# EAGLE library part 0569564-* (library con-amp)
MODULAR JACK 8 POS., RIGHT ANGLE, LOW PROFILE WITH LEDS Source: http://ecommas.tycoelectronics.com/.. 569564_K.pdf
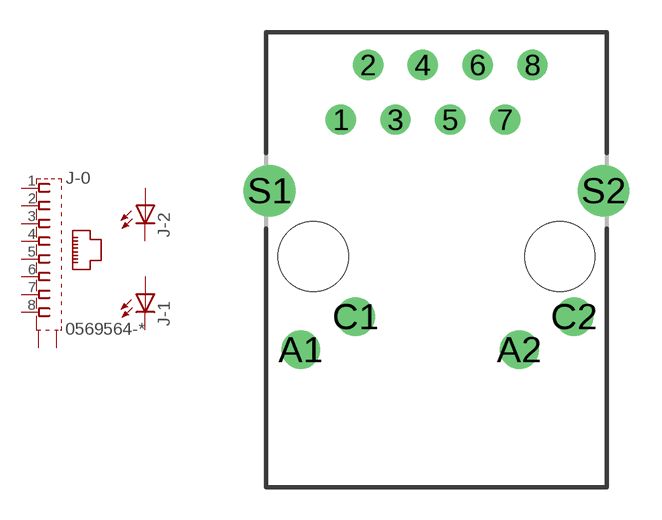
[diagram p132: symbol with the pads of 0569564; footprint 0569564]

Designator prefix J; gates -0=JACK8SH -1=LED -2=LED

## 0569564-1 (MF: TYCO ELECTRONICS; MPN: 569564-1; OC_FARNELL: 1375079; OC_NEWARK: 34B457), 0569564-2 (OC_FARNELL: unknown; OC_NEWARK: unknown), 0569564-4 (MF: TYCO ELECTRONICS; MPN: 569564-4; OC_FARNELL: unknown; OC_NEWARK: 57J1343)  [0569564]
1  -0:1  pas
2  -0:2  pas
3  -0:3  pas
4  -0:4  pas
5  -0:5  pas
6  -0:6  pas
7  -0:7  pas
8  -0:8  pas
A1  -1:A  pas
A2  -2:A  pas
C1  -1:C  pas
C2  -2:C  pas
S1  -0:S1  pas
S2  -0:S2  pas

## Footprint 0569564 (pad centres in mm)
Modular Jack 8 Position right angle, low profile, panel ground with LEDS Source: http://ecommas.tycoelectronics.com/.. 569564_K.pdf
drill 0.9 round: 1 -4.445,6.35; 2 -3.175,8.89; 3 -1.905,6.35; 4 -0.635,8.89; 5 0.635,6.35; 6 1.905,8.89; 7 3.175,6.35; 8 4.445,8.89
drill 1.2 round: A1 -6.295,-4.32; A2 3.835,-4.32; C1 -3.755,-2.79; C2 6.375,-2.79
drill 1.6 round: S1 -7.745,3.05; S2 7.745,3.05
hole 3.25 at -5.715,0
hole 3.25 at 5.715,0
